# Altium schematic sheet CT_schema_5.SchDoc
size 221 x 258 mm
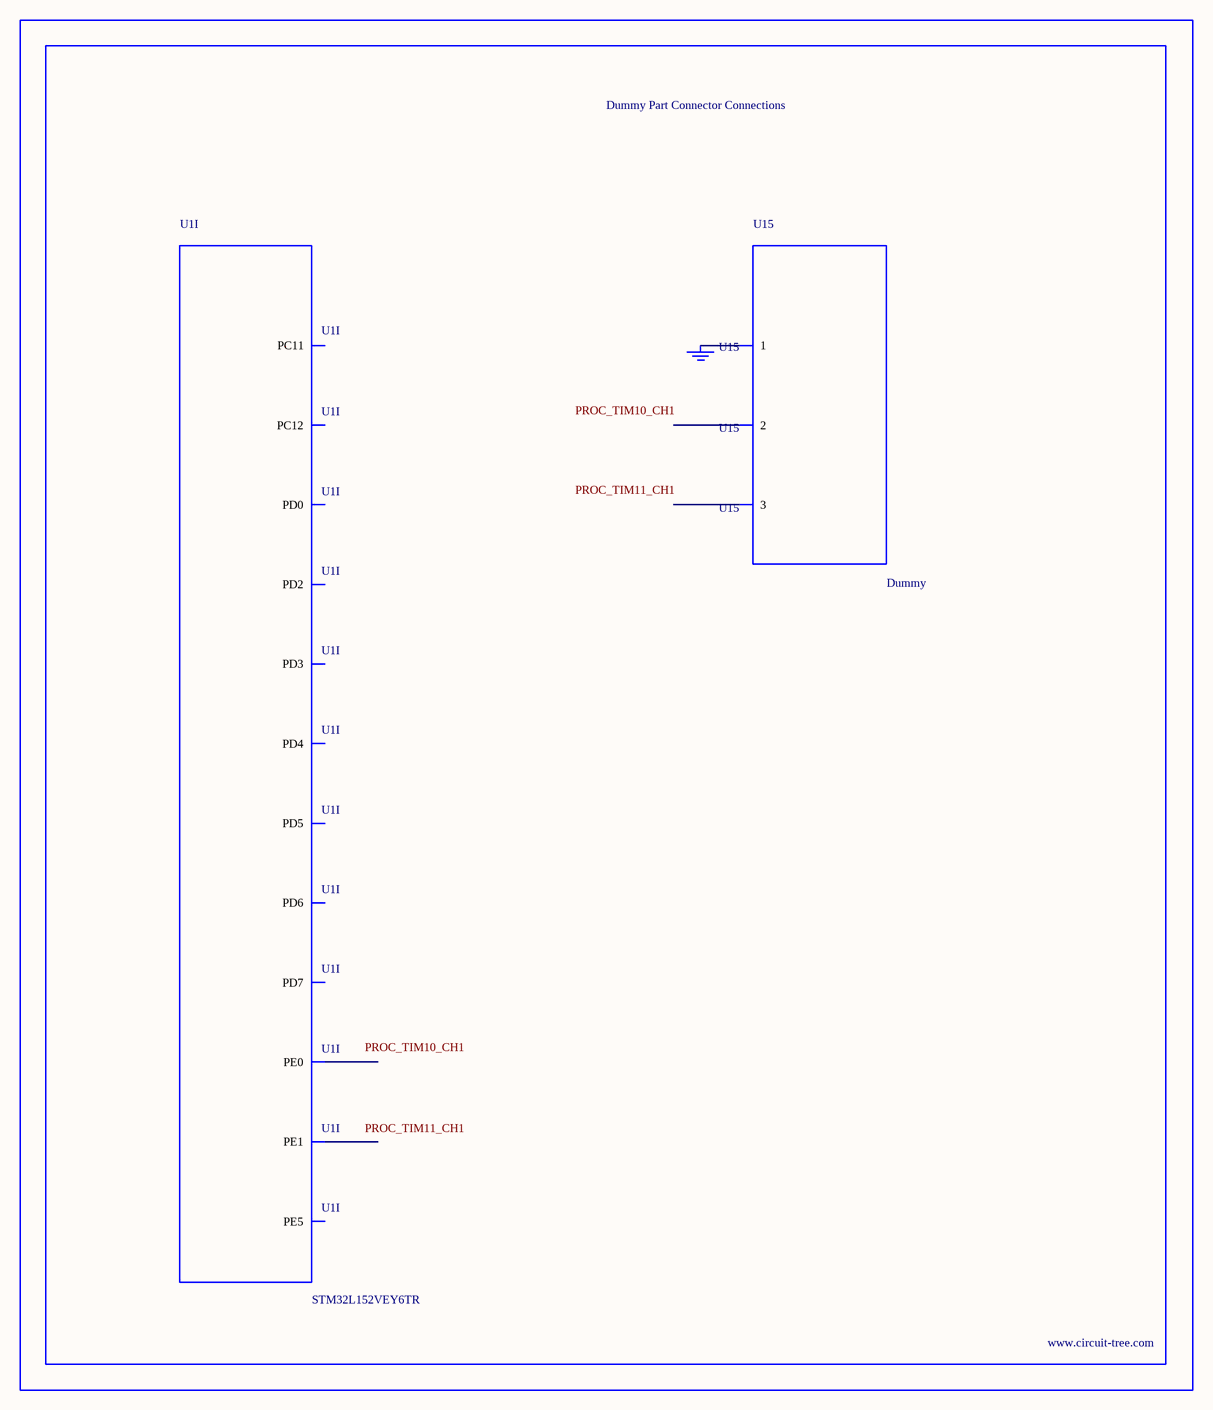
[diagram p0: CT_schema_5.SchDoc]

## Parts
BORDER4  (no value)
GND_INSTANCE_4_0  (no value)
U1  STM32L152VEY6TR  [WLCSP104]  (part I of 9)
U15  Dummy  [DUMMY_PACKAGE_128]

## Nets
NetGND_INSTANCE_4_0_0: GND_INSTANCE_4_0.0(GND) U15.1

Not connected (* = marked no-connect by the designer): U1 A2(PD0) A3(PD4) A4(PD7) A8(PE1) B2(PC12) B3(PD5) B4(PD6) B7(PE0) B9(PE5) C2(PC11) C3(PD2) C4(PD3); U15 2 3

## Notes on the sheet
- Labels drawn without touching a wire or pin: PROC_TIM10_CH1, PROC_TIM11_CH1

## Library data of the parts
BORDER4 = BORDER_PAGE4
GND_INSTANCE_4_0 = GND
